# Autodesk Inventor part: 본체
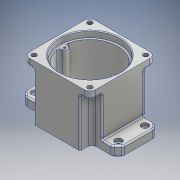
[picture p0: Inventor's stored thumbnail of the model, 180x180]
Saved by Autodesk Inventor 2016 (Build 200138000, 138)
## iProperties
Created: 2017-01
Part Number: 본체
Material: 알루미늄 6061
Document SubType Name: Modeling
Designer: Owner
Density: 2.7 g/cm^3
Appearance: 알루미늄 - 평지
Mass: 876.679 g
Surface Area: 765.057 cm^2
Volume: 324.696 cm^3
Author: Owner
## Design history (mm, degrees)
sketch "스케치1"
  geometry: L1 (-47, 47)-(47, 47); L2 (47, -47)-(-47, -47); L3 (-47, 47)-(47, -47); L4 (47, 47)-(-47, -47); L5 (70, 30)-(70, -30); L6 (-70, -30)-(-70, 30); L7 (-70, 30)-(70, -30); L8 (70, 30)-(-70, -30); L9 (-70, 30)-(-47, 30); L10 (47, 30)-(70, 30); L11 (47, 47)-(47, 30); L12 (47, -30)-(47, -47); L13 (70, -30)-(47, -30); L14 (-47, -30)-(-70, -30); L15 (-47, -47)-(-47, -30); L16 (-47, 30)-(-47, 47); L17 (0, 85.865)-(0, -117.389); L18 (-109.762, 0)-(188.446, 0); 3 further points
  constraints: 36 end point, 10 parallel, 6 midpoint, 4 horizontal, 4 perpendicular, 2 point on line, 1 vertical, 2 other
  dimensions: "d1" = 94 distance between parallel lines of L2 L1; "d4" = 140 distance between parallel lines of L6 L5; "d5" = 60 distance between parallel lines of L13 L10; "d6" = 60 distance of L6.start L6.end; "d7" = 94 distance of L1.start L1.end; "d8" = 94 distance of L2.start L2.end
extrude "돌출1" new body sketch "스케치1" distance "d9" = 13; taper "d10" = 0 deg
sketch "스케치2"
  geometry: L1 (-47, 47)-(47, 47); L2 (47, 47)-(47, -47); L3 (47, -47)-(-47, -47); L4 (-47, -47)-(-47, 47); L5 (-47, 47)-(47, -47); L6 (47, 47)-(-47, -47); 1 further point
  constraints: 12 end point, 2 midpoint, 2 parallel, 1 horizontal, 1 perpendicular
  dimensions: "d11" = 94 distance of L1.end L2.end; "d12" = 94 distance of L1.start L1.end
extrude "돌출2" join sketch "스케치2" distance "d13" = 67; taper "d14" = 0 deg
sketch "스케치3"
  geometry: L1 (47, -47)-(47, -30) reference; L2 (47, -47)-(33, -47); L3 (33, -47)-(33, -30); L4 (33, -30)-(47, -30); L5 (47, -30)-(47, -47); L6 (47, -30)-(70, -30) reference; L7 (47, 30)-(47, 47) reference; L8 (47, 47)-(33, 47); L9 (33, 47)-(33, 30); L10 (33, 30)-(47, 30); L11 (47, 30)-(47, 47); L12 (70, 30)-(47, 30) reference; 1 further point
  constraints: 16 end point, 4 parallel, 2 horizontal, 2 perpendicular
  dimensions: "d15" = 14 distance of L1.start L2.end; "d16" = 0 distance between parallel lines of L6 L4; "d17" = 14 distance of L7.end L8.end; "d18" = 0 distance between parallel lines of L12 L10
extrude "돌출3" cut sketch "스케치3" distance "d19" = 70; taper "d20" = 0 deg
sketch "스케치4"
  geometry: C1 r 40 at (0, 0); 1 further point
  constraints: 1 centre point, 1 coincident
  dimensions: "d21" = 80 diameter of C1
extrude "돌출4" cut sketch "스케치4" distance "d22" = 71; taper "d23" = 0 deg
sketch "스케치5"
  geometry: C1 r 43 at (0, 0); 1 further point
  constraints: 1 centre point, 1 coincident
  dimensions: "d24" = 86 diameter of C1
extrude "돌출5" cut sketch "스케치5" distance "d25" = 9; taper "d26" = 0 deg
sketch "스케치6"
  geometry: A1 r 21 centre (0, 11) between (8.978, -7.984) and (-8.978, -7.984); A2 r 15 centre (0, -20) between (-8.978, -7.984) and (8.978, -7.984); 1 further point
  constraints: 4 point on circle, 2 centre point, 2 vertical alignment
  dimensions: "d27" = 42 diameter of A1; "d28" = 11 distance of A1.centre point (0, 0); "d29" = 30 diameter of A2; "d30" = 20 distance of point (0, 0) A2.centre
extrude "돌출6" join sketch "스케치6" distance "d31" = 7; taper "d32" = 0 deg
sketch "스케치8"
  geometry: C1 r 27.5 at (0, 11); 1 further point
  constraints: 1 centre point, 1 vertical alignment
  dimensions: "d40" = 11 distance of point (0, 0) C1.centre; "d41" = 55 diameter of C1
extrude "돌출7" join sketch "스케치8" distance "d42" = 7; taper "d43" = 0 deg
sketch "스케치9"
  geometry: L1 (-16.5, -7)-(38.5, -7) reference; L2 (32, 16)-(-7.984, 16) reference; L3 (11, 16)-(11, -7); L4 (11, -7)-(27, -7); L5 (27, -7)-(27, 1); L6 (27, 1)-(23.5, 1); L7 (23.5, 1)-(23.5, 6); L8 (23.5, 6)-(28.5, 6); L9 (28.5, 6)-(28.5, 16); L10 (28.5, 16)-(11, 16); 1 further point
  constraints: 16 end point, 5 perpendicular, 3 point on line, 1 collinear, 1 midpoint, 1 vertical
  dimensions: "d44" = 11 distance from line of point (0, 0) L3; "d45" = 8 distance of L4.end L5.end; "d46" = 5 distance of L6.end L7.end; "d47" = 32 diameter of L5 L3; "d48" = 25 diameter of L7 L3; "d49" = 35 diameter of L9 L3
revolve "회전1" sketch "스케치9" stored, may be unused: angle "d50" = 90 deg
hole "구멍1" diameter "d53" = 19; stored, may be unused: countersink angle "d57" = 90 deg, drill point angle "d59" = 0 deg; dims "d54" = 6, "d55" = 22, "d56" = 7, "d58" = 8, "d60" = 10, "d61" = 10
sketch "스케치10"
  geometry: L1 (33.144, 0)-(33.144, 3.683); L2 (33.144, 0)-(33.144, -3.683); A1 r 40 centre (0, 0) between (39.148, 8.214) and (39.148, -8.214) reference; A2 r 4 centre (36, 0) between (35.852, 3.997) and (35.852, -3.997); A3 r 3.5 centre (35.722, 7.495) between (35.852, 3.997) and (39.148, 8.214); A4 r 3.5 centre (35.722, -7.495) between (39.148, -8.214) and (35.852, -3.997); 1 further point
  constraints: 8 point on circle, 4 end point, 4 tangent, 3 centre point, 2 horizontal alignment, 2 vertical, 1 point on line
  dimensions: "d68" = 8 diameter of A2; "d69" = 36 distance of point (0, 0) A2.centre; "d70" = 7 diameter of A3; "d71" = 7 diameter of A4
extrude "돌출9" join sketch "스케치10" stored distance "d72" = 7; taper "d73" = 0 deg
fillet "모깎기1" dims "d74" = 8
chamfer "모따기1" distance "d75" = 8; stored, may be unused: second distance "d76" = 2, angle "d77" = 45 deg
fillet "모깎기2" dims "d96" = 5
fillet "모깎기3" dims "d97" = 5
fillet "모깎기4" dims "d98" = 2
fillet "모깎기5" dims "d99" = 2
fillet "모깎기7" dims "d101" = 2
fillet "모깎기8" dims "d102" = 2
fillet "모깎기9" dims "d103" = 2
fillet "모깎기10" dims "d104" = 2
chamfer "모따기2" distance "d105" = 1; stored, may be unused: second distance "d106" = 2, angle "d107" = 45 deg
fillet "모깎기11" dims "d108" = 0.3
fillet "모깎기12" dims "d109" = 0.3
fillet "모깎기13" dims "d110" = 2
fillet "모깎기14" dims "d111" = 3
fillet "모깎기15" dims "d112" = 2
fillet "모깎기16" dims "d113" = 2
hole "구멍4" diameter "d116" = 3.242; stored, may be unused: countersink angle "d120" = 90 deg, drill point angle "d122" = 118 deg; dims "d117" = 7, "d118" = 22, "d119" = 7, "d121" = 9, "d153" = 10, "d154" = 10
chamfer "모따기3" distance "d123" = 1; stored, may be unused: second distance "d124" = 2, angle "d125" = 45 deg
sketch "스케치12"
  geometry: L1 (-31, -47)-(31, -47) reference; L2 (33, -45)-(33, -35) reference; L3 (38, -30)-(59.929, -30) reference; L4 (68.536, -23.464)-(63.464, -28.536) reference; L5 (70, -19.929)-(70, 19.929) reference; L6 (63.464, 28.536)-(68.536, 23.464) reference; L7 (59.929, 30)-(38, 30) reference; L8 (33, 35)-(33, 45) reference; L9 (31, 47)-(-31, 47) reference; L10 (-33, 45)-(-33, 35) reference; L11 (-38, 30)-(-59.929, 30) reference; L12 (-68.536, 23.464)-(-63.464, 28.536) reference; L13 (-70, 19.929)-(-70, -19.929) reference; L14 (-63.464, -28.536)-(-68.536, -23.464) reference; L15 (-59.929, -30)-(-38, -30) reference; L16 (-33, -35)-(-33, -45) reference; L17 (-31, 46)-(31, 46); L18 (32, 45)-(32, 35); L19 (38, 29)-(59.929, 29); L20 (62.757, 27.828)-(67.828, 22.757); L21 (69, 19.929)-(69, -19.929); L22 (67.828, -22.757)-(62.757, -27.828); L23 (59.929, -29)-(38, -29); L24 (32, -35)-(32, -45); L25 (31, -46)-(-31, -46); L26 (-32, -45)-(-32, -35); L27 (-38, -29)-(-59.929, -29); L28 (-62.757, -27.828)-(-67.828, -22.757); L29 (-69, -19.929)-(-69, 19.929); L30 (-67.828, 22.757)-(-62.757, 27.828); L31 (-59.929, 29)-(-38, 29); L32 (-32, 35)-(-32, 45); C1 r 27.5 at (0, 11) reference; A1 r 2 centre (-31, -45) between (-33, -45) and (-31, -47) reference; A2 r 2 centre (31, -45) between (31, -47) and (33, -45) reference; A3 r 5 centre (38, -35) between (38, -30) and (33, -35) reference; A4 r 5 centre (59.929, -25) between (59.929, -30) and (63.464, -28.536) reference; A5 r 5 centre (65, -19.929) between (68.536, -23.464) and (70, -19.929) reference; A6 r 5 centre (65, 19.929) between (70, 19.929) and (68.536, 23.464) reference; A7 r 5 centre (59.929, 25) between (63.464, 28.536) and (59.929, 30) reference; A8 r 5 centre (38, 35) between (33, 35) and (38, 30) reference; A9 r 2 centre (31, 45) between (33, 45) and (31, 47) reference; A10 r 2 centre (-31, 45) between (-31, 47) and (-33, 45) reference; A11 r 5 centre (-38, 35) between (-38, 30) and (-33, 35) reference; A12 r 5 centre (-59.929, 25) between (-59.929, 30) and (-63.464, 28.536) reference; A13 r 5 centre (-65, 19.929) between (-68.536, 23.464) and (-70, 19.929) reference; A14 r 5 centre (-65, -19.929) between (-70, -19.929) and (-68.536, -23.464) reference; A15 r 5 centre (-59.929, -25) between (-63.464, -28.536) and (-59.929, -30) reference; A16 r 5 centre (-38, -35) between (-33, -35) and (-38, -30) reference; A17 r 1 centre (31, 45) between (32, 45) and (31, 46); A18 r 6 centre (38, 35) between (32, 35) and (38, 29); A19 r 4 centre (59.929, 25) between (62.757, 27.828) and (59.929, 29); A20 r 4 centre (65, 19.929) between (69, 19.929) and (67.828, 22.757); A21 r 4 centre (65, -19.929) between (67.828, -22.757) and (69, -19.929); A22 r 4 centre (59.929, -25) between (59.929, -29) and (62.757, -27.828); A23 r 6 centre (38, -35) between (38, -29) and (32, -35); A24 r 1 centre (31, -45) between (31, -46) and (32, -45); A25 r 1 centre (-31, -45) between (-32, -45) and (-31, -46); A26 r 6 centre (-38, -35) between (-32, -35) and (-38, -29); A27 r 4 centre (-59.929, -25) between (-62.757, -27.828) and (-59.929, -29); A28 r 4 centre (-65, -19.929) between (-69, -19.929) and (-67.828, -22.757); A29 r 4 centre (-65, 19.929) between (-67.828, 22.757) and (-69, 19.929); A30 r 4 centre (-59.929, 25) between (-59.929, 29) and (-62.757, 27.828); A31 r 6 centre (-38, 35) between (-38, 29) and (-32, 35); A32 r 1 centre (-31, 45) between (-31, 46) and (-32, 45); 1 further point
  constraints: 32 end point, 32 point on circle, 16 centre point, 31 other
  dimensions: "d126" = 1 distance between parallel lines of L9 L17
extrude "돌출10" cut sketch "스케치12" distance "d127" = 1; taper "d128" = 0 deg
sketch "스케치13"
  geometry: L1 (-70, 19.929)-(-70, -19.929) reference; L2 (-59.929, -30)-(-49, -30) reference; L3 (-49, 30)-(-59.929, 30) reference; 3 further points
  dimensions: "d129" = 10 distance from line of L1 point (-60, -19); "d130" = 11 distance from line of L2 point (-60, -19); "d131" = 10 distance from line of L1 point (-60, 19); "d132" = 11 distance from line of L3 point (-60, 19)
hole "구멍5" sketch "스케치13" at (-60, -19), (-60, 19) diameter "d133" = 4; stored, may be unused: countersink angle "d137" = 90 deg, drill point angle "d139" = 0 deg; dims "d134" = 7, "d135" = 10, "d136" = 4, "d138" = 9
sketch "스케치15"
  geometry: L1 (78, 0)-(0, 0) reference; 2 further points
  constraints: 1 vertical alignment, 1 other
  dimensions: "d140" = 40 distance from line of L1 point (39, 40)
feature "엠보싱1" sketch "스케치15" dims "d141" = 0.5, "d142" = 0
sketch "스케치16"
  geometry: L1 (0, 0)-(0, 61.21); 2 further points
  constraints: 2 end point, 1 symmetric about line, 1 vertical
  dimensions: "d143" = 40 horizontal distance of L1.start point (40, 40); "d144" = 40 horizontal distance of L1.start point (40, 40)
hole "구멍6" sketch "스케치16" at (40, 40), (-40, 40) diameter "d145" = 7; stored, may be unused: countersink angle "d149" = 90 deg, drill point angle "d151" = 0 deg; dims "d146" = 7, "d147" = 10, "d148" = 4, "d150" = 9
fillet "모깎기17" dims "d152" = 0.3
node "솔리드1"
mirror "대칭1"
mirror "대칭2"
mirror "대칭4"
mirror "대칭5"
mirror "대칭6"
node "투영된 루프1"
other parameters: "d2" = 94
